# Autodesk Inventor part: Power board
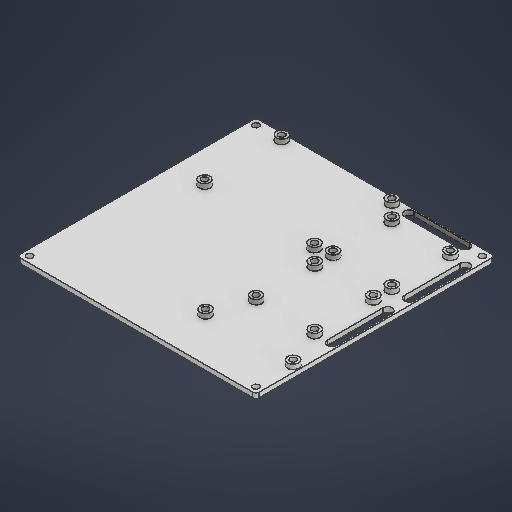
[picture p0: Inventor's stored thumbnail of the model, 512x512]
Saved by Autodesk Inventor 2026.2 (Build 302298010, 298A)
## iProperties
Created: 2026-04
Part Number: Power board
Material: 일반
Document SubType Name: Modeling
Designer: work
Density: 1 g/cm^3
Appearance: 기본값
Author: work
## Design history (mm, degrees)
sketch "스케치1"
  geometry: L1 (0, -150)-(150, -150); L2 (150, -150)-(150, 0); L3 (150, 0)-(0, 0); L4 (0, 0)-(0, -150); L5 (0, -150)-(150, 0); L6 (150, -150)-(0, 0); L7 (4, -4)-(146, -4); L8 (146, -4)-(146, -146); L9 (146, -146)-(4, -146); L10 (4, -146)-(4, -4); L11 (4, -4)-(146, -146); L12 (146, -4)-(4, -146); L13 (50.8, -99.2)-(50.8, -136); L14 (14, -99.2)-(50.8, -99.2); L15 (50.8, -136)-(14, -136); L16 (14, -136)-(14, -99.2); L17 (14, -99.2)-(50.8, -136); L18 (50.8, -99.2)-(14, -136); L19 (32.4, -117.6)-(32.4, -146); L20 (49.9, -143)-(14.9, -143); L21 (14.9, -146)-(49.9, -146); L22 (14.9, -149)-(49.9, -149); L23 (32.4, -69.232)-(4, -69.232); L24 (14, -87.632)-(14, -50.832); L25 (14, -50.832)-(50.8, -50.832); L26 (50.8, -87.632)-(14, -87.632); L27 (50.8, -50.832)-(14, -87.632); L28 (50.8, -50.832)-(50.8, -87.632); L29 (50.8, -87.632)-(14, -50.832); L30 (4, -86.732)-(4, -51.732); L31 (7, -86.732)-(7, -51.732); L32 (1, -51.732)-(1, -86.732); L33 (60.8, -146)-(60.8, -97.5); L34 (60.8, -97.5)-(129.8, -97.5); L35 (129.8, -146)-(60.8, -146); L36 (129.8, -97.5)-(60.8, -146); L37 (129.8, -97.5)-(129.8, -146); L38 (60.8, -97.5)-(129.8, -146); L39 (8.5, -13.832)-(54.5, -13.832); L40 (54.5, -13.832)-(8.5, -40.832); L41 (54.5, -13.832)-(54.5, -40.832); L42 (59, -27.332)-(4, -27.332); L43 (8.5, -13.832)-(54.5, -40.832); L44 (8.5, -40.832)-(8.5, -13.832); L45 (54.5, -40.832)-(8.5, -40.832); L46 (4, -135.1)-(4, -100.1); L47 (7, -135.1)-(7, -100.1); L48 (1, -100.1)-(1, -135.1); C1 r 2 at (50.8, -99.2); C2 r 2 at (14, -99.2); C3 r 2 at (14, -136); C4 r 2 at (50.8, -136); C5 r 2 at (14, -50.832); C6 r 2 at (14, -87.632); C7 r 2 at (50.8, -50.832); C8 r 2 at (50.8, -87.632); C9 r 2 at (60.8, -97.5); C10 r 2 at (129.8, -97.5); C11 r 2 at (60.8, -146); C12 r 2 at (129.8, -146); C13 r 2 at (59, -27.332); C14 r 2 at (4, -27.332); C15 r 2 at (4, -4); C16 r 2 at (4, -146); C17 r 2 at (146, -146); C18 r 2 at (146, -4); A1 r 3 centre (49.9, -146) between (49.9, -149) and (49.9, -143); A2 r 3 centre (14.9, -146) between (14.9, -143) and (14.9, -149); A3 r 3 centre (4, -51.732) between (7, -51.732) and (1, -51.732); A4 r 3 centre (4, -86.732) between (1, -86.732) and (7, -86.732); A5 r 3 centre (4, -135.1) between (1, -135.1) and (7, -135.1); A6 r 3 centre (4, -100.1) between (7, -100.1) and (1, -100.1); 6 further points
  constraints: 102 end point, 24 centre point, 19 coincident, 17 midpoint, 15 parallel, 12 point on circle, 12 tangent, 8 horizontal, 7 point on line, 6 perpendicular, 2 vertical
  dimensions: "d0" = 150 distance of L3.end L2.end; "d1" = 150 distance of L2.end L1.end; "d2" = 4 distance between parallel lines of L2 L8; "d3" = 36.8 distance of L13.end L15.end; "d4" = 36.8 distance of L13.start L13.end; "d5" = 4 diameter of C2; "d6" = 4 diameter of C3; "d7" = 4 diameter of C4; "d8" = 4 diameter of C1; "d9" = 6 diameter of A1; "d10" = 35 distance of L21.start L21.end; "d11" = 10 horizontal distance of L9.end C3.centre; "d12" = 10 horizontal distance of L9.end L15.end; "d13" = 36.8 distance of L24.start L24.end; "d14" = 36.8 distance of L26.start L24.start; "d15" = 4 diameter of C7; "d16" = 4 diameter of C5; "d17" = 4 diameter of C6; "d18" = 4 diameter of C8; "d19" = 6 diameter of A3; "d20" = 35 distance of L30.start L30.end; "d21" = 28.4 distance of L23.start L23.end; "d22" = 69 distance of L35.start L33.start; "d23" = 48.5 distance of L34.end L35.start; "d24" = 4 diameter of C9; "d25" = 4 diameter of C11; "d26" = 4 diameter of C12; "d27" = 4 diameter of C10; "d28" = 10 distance between parallel lines of L13 L33; "d29" = 11.56791 distance between parallel lines of L14 L26; "d30" = 55 distance of L42.start L42.end; "d31" = 46 distance of L41.end L40.end; "d32" = 27 distance of L39.end L41.end; "d33" = 4 diameter of C13; "d34" = 4 diameter of C14; "d35" = 10 distance between parallel lines of L25 L45; "d36" = 4 diameter of C15; "d37" = 4 diameter of C16; "d38" = 4 diameter of C17; "d39" = 4 diameter of C18; "d40" = 17.5 distance of point (4, -117.6) L46.end; "d41" = 6 diameter of A6
extrude "돌출1" new body sketch "스케치1" distance "d42" = 3; taper "d43" = 0 deg
sketch "스케치2"
  geometry: L1 (-7, 100.1)-(-7, 135.1) reference; L2 (-150, 150)-(-150, 0) reference; L3 (-150, 0)-(0, 0) reference; L4 (0, 0)-(0, 150) reference; L5 (0, 150)-(-150, 150) reference; L6 (-1, 135.1)-(-1, 100.1) reference; L7 (-7, 100.1)-(-7, 135.1) reference; L8 (-7, 51.732)-(-7, 86.732) reference; L9 (-1, 86.732)-(-1, 51.732) reference; L10 (-49.9, 149)-(-14.9, 149) reference; L11 (-14.9, 143)-(-49.9, 143) reference; C1 r 2 at (-146, 4) reference; C2 r 2 at (-4, 146) reference; C3 r 2 at (-4, 27.332) reference; C4 r 2 at (-129.8, 146) reference; C5 r 2 at (-129.8, 97.5) reference; C6 r 2 at (-50.8, 87.632) reference; C7 r 2 at (-50.8, 50.832) reference; C8 r 2 at (-14, 87.632) reference; C9 r 2 at (-14, 50.832) reference; C10 r 2 at (-50.8, 136) reference; C11 r 2 at (-14, 136) reference; C12 r 2 at (-14, 99.2) reference; C13 r 2 at (-50.8, 99.2) reference; C14 r 2 at (-60.8, 97.5) reference; C15 r 2 at (-60.8, 146) reference; C16 r 2 at (-59, 27.332) reference; C17 r 2 at (-4, 4) reference; C18 r 2 at (-146, 146) reference; C19 r 2 at (-14, 87.632) reference; C20 r 2 at (-14, 50.832) reference; C21 r 2 at (-129.8, 146) reference; C22 r 3.5 at (-4, 27.332); A1 r 3 centre (-4, 135.1) between (-1, 135.1) and (-7, 135.1) reference; A2 r 3 centre (-4, 100.1) between (-7, 100.1) and (-1, 100.1) reference; A3 r 3 centre (-4, 86.732) between (-1, 86.732) and (-7, 86.732) reference; A4 r 3 centre (-4, 51.732) between (-7, 51.732) and (-1, 51.732) reference; A5 r 3 centre (-14.9, 146) between (-14.9, 143) and (-14.9, 149) reference; A6 r 3 centre (-49.9, 146) between (-49.9, 149) and (-49.9, 143) reference; 15 further points
  constraints: 15 coincident, 1 centre point
  dimensions: "d44" = 7 diameter of C22
  node "투영된 루프1"
extrude "돌출2" join sketch "스케치2" distance "d45" = 3; taper "d46" = 0 deg
fillet "모깎기1" dims "d47" = 2
node "솔리드1"
feature "스케치 연계 패턴1"
